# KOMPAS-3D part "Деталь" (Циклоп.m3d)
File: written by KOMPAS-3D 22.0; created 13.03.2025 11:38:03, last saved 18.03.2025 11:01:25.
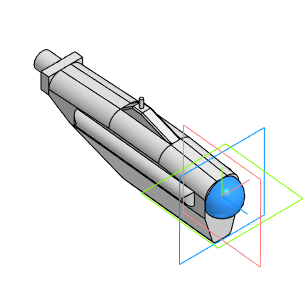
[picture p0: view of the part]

Document properties: Автор: Пользователь Windows; Полное имя файла: C:\Users\Student\Documents\Картошечка\База Сабнатика\Циклоп.m3d

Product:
- Body: Тело 1
    Масса: 0.476079
- Body: Тело 2
    Масса: 0.012257
- Part/product: Деталь
    Масса: 0.488336

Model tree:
1. Эскиз:1
2. Элемент вращения:1
     Угол 1 = 180
3. Эскиз:2
4. Элемент выдавливания:1
     Расстояние 1 = 20
5. Эскиз:3  (with: Элемент выдавливания:1)
6. Элемент выдавливания:3
     Расстояние 2 = 94
7. Эскиз:4  (with: Элемент выдавливания:1)
8. Элемент выдавливания:4
     Расстояние 1 = 4
9. Зеркальный массив:1
10. Экземпляр ( 1 )
11. Экземпляр ( 2 )  (with: Элемент выдавливания:4)
12. Скругление:1  (with: Элемент выдавливания:1)
     Радиус = 7
13. Скругление:2  (with: Элемент выдавливания:4)
     Радиус = 4
14. Эскиз:6  (with: Скругление:1)
15. Элемент выдавливания:5
     Расстояние 1 = 6
16. Эскиз:7  (with: Элемент выдавливания:5)
17. Элемент выдавливания:6
     Расстояние 1 = 5
18. Скругление:3  (with: Элемент выдавливания:5)
     Радиус = 0.7
19. Плоскость через ребро и точку:1  (with: Элемент выдавливания:1)
20. Смещенная плоскость:1
     Расстояние = 5
21. Эскиз:11
22. Элемент выдавливания:7  (with: Элемент выдавливания:1)
     Расстояние 1 = 5
23. Эскиз:12  (with: Элемент выдавливания:7)
24. Элемент выдавливания:8
     Расстояние 1 = 10
25. Эскиз:13  (with: Элемент выдавливания:8)
26. Элемент выдавливания:9
     Расстояние 2 = 5
27. Эскиз:14  (with: Элемент выдавливания:1)
28. Элемент выдавливания:10
     Расстояние 2 = 1
29. Скругление:4  (with: Элемент выдавливания:3)
     Радиус = 2
30. Эскиз:15  (with: Элемент выдавливания:1, Скругление:4)
31. Элемент выдавливания:11
     Расстояние 2 = 1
